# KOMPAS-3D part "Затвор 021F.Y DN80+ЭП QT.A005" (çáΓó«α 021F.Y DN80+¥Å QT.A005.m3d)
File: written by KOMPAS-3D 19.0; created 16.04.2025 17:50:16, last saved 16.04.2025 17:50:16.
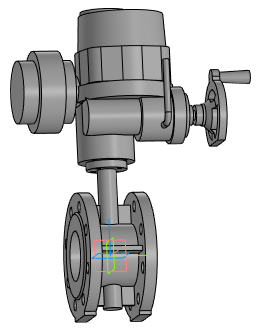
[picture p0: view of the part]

Document properties: Полное имя файла: Затвор 021F.Y DN80+ЭП QT.A005.a3d

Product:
- Part/product: Затвор 021F.Y DN80+ЭП QT.A005
    Масса: 46.9977

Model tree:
1. Операция без истории:1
